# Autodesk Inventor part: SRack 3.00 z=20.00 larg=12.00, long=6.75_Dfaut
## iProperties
Created: 2007-07
Part Number: SRack 3.00 z=20.00 larg=12.00, long=6.75_Dfaut
Document SubType Name: Modeling
Designer: EF
Density: 1 g/cm^3
Author: EF
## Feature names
1. Base1
